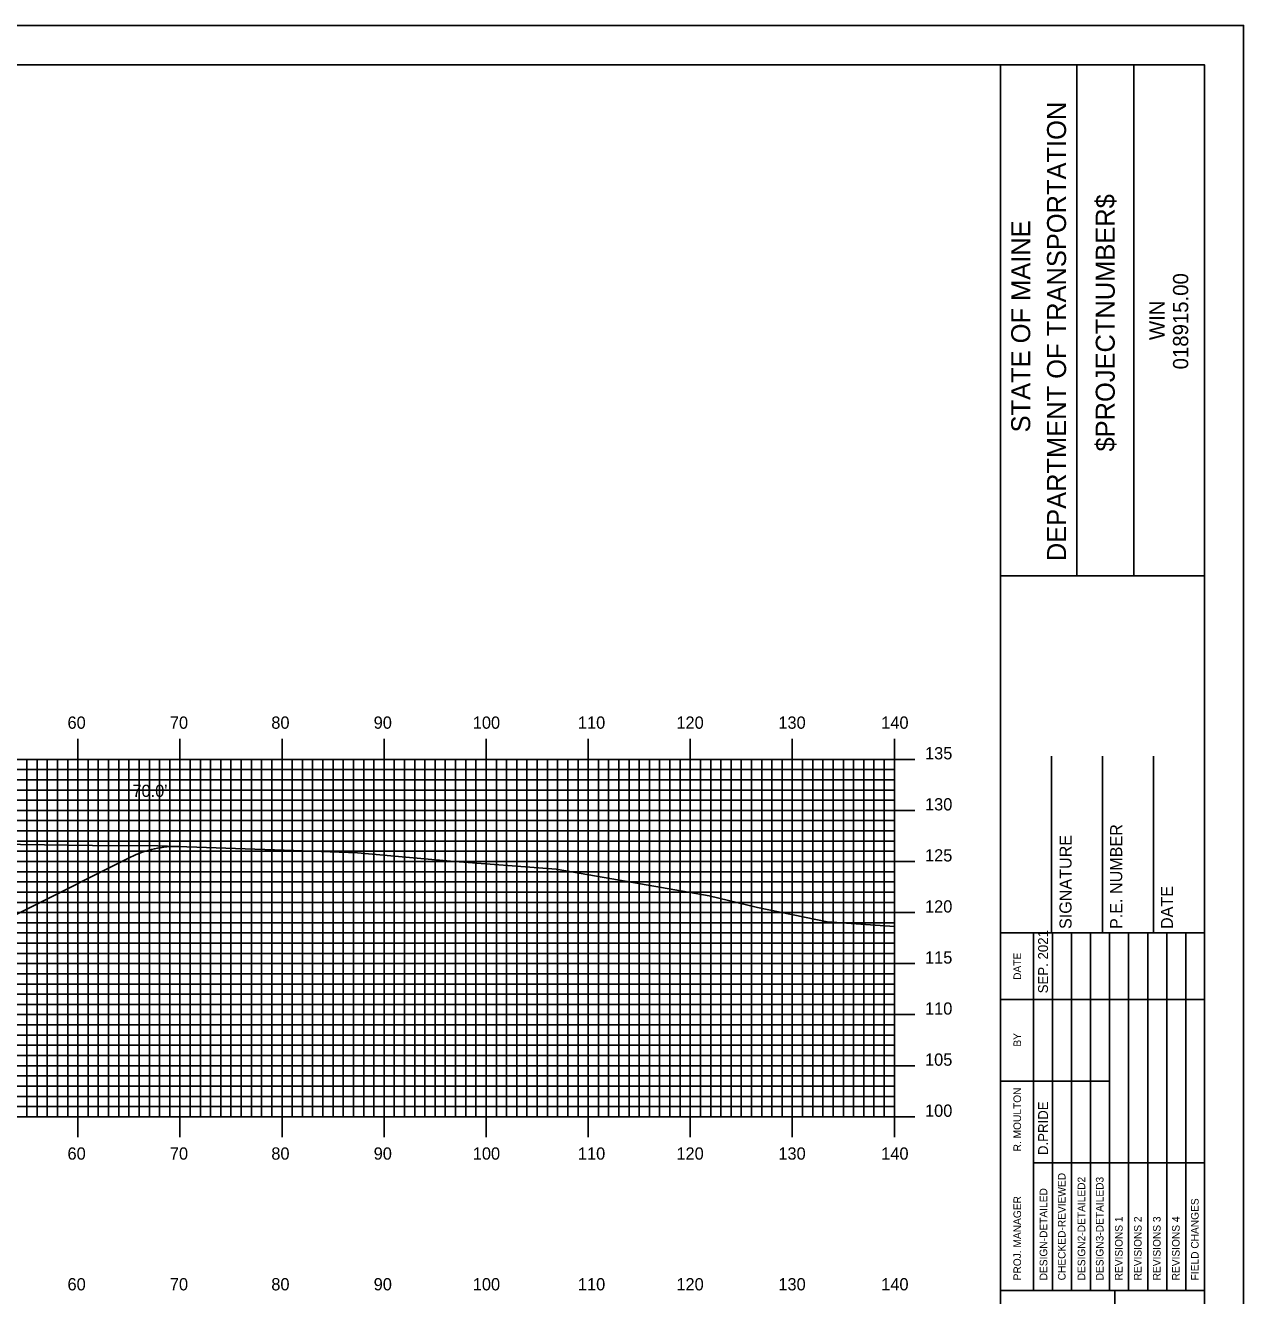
# Model space of a CAD drawing. Extents: x 1766907 to 1767250, y 442591 to 442811.
# Drawn here: x 1767127.3 to 1767246.6, y 442686.2 to 442810.5 of the extents above; entities that cross this region are included whole.
import ezdxf

# ---------------------------------------------------------------- set-up
doc = ezdxf.new("R2010")
doc.units = 0
for name, color, linetype in [('BORDER', 7, 'Continuous'), ('D_Roadway_Centerline', 7, 'Continuous'), ('D_Roadway_SlopeLines', 7, 'Continuous'), ('D_Text_Standard', 7, 'Continuous'), ('H_V ANNOTATION', 7, 'Continuous'), ('MAJOR', 7, 'Continuous'), ('MINOR', 7, 'Continuous'), ('PLOT BOUNDARY', 7, 'Continuous'), ('S_Roadway_Centerline', 7, 'Continuous')]:
    doc.layers.add(name, color=color, linetype=linetype)

msp = doc.modelspace()

# ---------------------------------------------------------------- linework, layer by layer
at = {"layer": 'BORDER'}
for p, q in [((1767222.82, 442596.67), (1767222.82, 442806.67)), ((1767230.28, 442756.66), (1767230.28, 442806.66)), ((1767235.87, 442756.66), (1767235.87, 442806.66)), ((1767222.83, 442756.65), (1767242.82, 442756.65)), ((1767227.82, 442721.67), (1767227.82, 442738.97)), ((1767232.82, 442721.67), (1767232.82, 442738.97)), ((1767237.82, 442721.67), (1767237.82, 442738.97)), ((1767222.82, 442721.67), (1767242.82, 442721.67)), ((1767222.82, 442686.67), (1767242.82, 442686.67)), ((1767234.01, 442616.67), (1767234.01, 442686.67))]:
    msp.add_line(p, q, dxfattribs=at)
msp.add_lwpolyline([(1766922.82, 442596.67), (1767242.82, 442596.67), (1767242.82, 442806.67), (1766922.82, 442806.67)], close=True, dxfattribs=at)
for points in [[(1767226.05, 442715.17), (1767226.05, 442721.67)], [(1767227.92, 442686.68), (1767227.92, 442721.67)], [(1767229.78, 442721.67), (1767229.78, 442686.68)], [(1767231.64, 442686.68), (1767231.64, 442721.67)], [(1767233.51, 442686.68), (1767233.51, 442721.67)], [(1767235.37, 442686.68), (1767235.37, 442721.67)], [(1767237.24, 442686.68), (1767237.24, 442721.67)], [(1767239.1, 442686.68), (1767239.1, 442721.67)], [(1767240.96, 442686.68), (1767240.96, 442721.67)], [(1767226.05, 442686.68), (1767226.05, 442720.26)], [(1767222.82, 442715.17), (1767242.82, 442715.17)], [(1767222.82, 442707.17), (1767226.05, 442707.17)], [(1767226.05, 442707.17), (1767233.51, 442707.17)], [(1767226.05, 442699.17), (1767242.82, 442699.17)]]:
    msp.add_lwpolyline(points, dxfattribs=at)
at = {"layer": 'D_Roadway_Centerline'}
msp.add_arc((1767142.05, 442720.14), 10, 88.0666, 116.5694, dxfattribs=at)
at = {"layer": 'D_Roadway_SlopeLines'}
msp.add_lwpolyline([(1767106.6, 442713.59), (1767137.58, 442729.09)], dxfattribs=at)
at = {"layer": 'MAJOR'}
for p, q in [((1767132.42, 442740.67), (1767132.42, 442738.67)), ((1767142.42, 442740.67), (1767142.42, 442738.67)), ((1767152.42, 442740.67), (1767152.42, 442738.67)), ((1767162.42, 442740.67), (1767162.42, 442738.67)), ((1767172.42, 442740.67), (1767172.42, 442738.67)), ((1767182.42, 442740.67), (1767182.42, 442738.67)), ((1767192.42, 442740.67), (1767192.42, 442738.67)), ((1767202.42, 442740.67), (1767202.42, 442738.67)), ((1767212.42, 442740.67), (1767212.42, 442738.67)), ((1766932.42, 442738.67), (1767212.42, 442738.67)), ((1766932.42, 442738.67), (1767212.42, 442738.67)), ((1767132.42, 442703.67), (1767132.42, 442738.67)), ((1767142.42, 442703.67), (1767142.42, 442738.67)), ((1767152.42, 442703.67), (1767152.42, 442738.67)), ((1767162.42, 442703.67), (1767162.42, 442738.67)), ((1767172.42, 442703.67), (1767172.42, 442738.67)), ((1767182.42, 442703.67), (1767182.42, 442738.67)), ((1767192.42, 442703.67), (1767192.42, 442738.67)), ((1767202.42, 442703.67), (1767202.42, 442738.67)), ((1767214.43, 442738.67), (1767210.42, 442738.67)), ((1767212.42, 442703.67), (1767212.42, 442738.67)), ((1767212.42, 442703.67), (1767212.42, 442738.67)), ((1766932.42, 442733.67), (1767212.42, 442733.67)), ((1767214.43, 442733.67), (1767210.42, 442733.67)), ((1766932.42, 442728.67), (1767212.42, 442728.67)), ((1767214.43, 442728.67), (1767210.42, 442728.67)), ((1766932.42, 442723.67), (1767212.42, 442723.67)), ((1767214.43, 442723.67), (1767210.42, 442723.67)), ((1766932.42, 442718.67), (1767212.42, 442718.67)), ((1767214.43, 442718.67), (1767210.42, 442718.67)), ((1766932.42, 442713.67), (1767212.42, 442713.67)), ((1767214.43, 442713.67), (1767210.42, 442713.67)), ((1766932.42, 442708.67), (1767212.42, 442708.67)), ((1767214.43, 442708.67), (1767210.42, 442708.67)), ((1766932.42, 442703.67), (1767212.42, 442703.67)), ((1766932.42, 442703.67), (1767212.42, 442703.67)), ((1767132.42, 442701.66), (1767132.42, 442703.67)), ((1767142.42, 442701.66), (1767142.42, 442703.67)), ((1767152.42, 442701.66), (1767152.42, 442703.67)), ((1767162.42, 442701.66), (1767162.42, 442703.67)), ((1767172.42, 442701.66), (1767172.42, 442703.67)), ((1767182.42, 442701.66), (1767182.42, 442703.67)), ((1767192.42, 442701.66), (1767192.42, 442703.67)), ((1767202.42, 442701.66), (1767202.42, 442703.67)), ((1767214.43, 442703.67), (1767210.42, 442703.67)), ((1767212.42, 442701.66), (1767212.42, 442703.67))]:
    msp.add_line(p, q, dxfattribs=at)
at = {"layer": 'MINOR'}
for p, q in [((1766932.42, 442737.67), (1767212.42, 442737.67)), ((1767127.42, 442703.67), (1767127.42, 442738.67)), ((1767128.42, 442703.67), (1767128.42, 442738.67)), ((1767129.42, 442703.67), (1767129.42, 442738.67)), ((1767130.42, 442703.67), (1767130.42, 442738.67)), ((1767131.42, 442703.67), (1767131.42, 442738.67)), ((1767133.42, 442703.67), (1767133.42, 442738.67)), ((1767134.42, 442703.67), (1767134.42, 442738.67)), ((1767135.42, 442703.67), (1767135.42, 442738.67)), ((1767136.42, 442703.67), (1767136.42, 442738.67)), ((1767137.42, 442703.67), (1767137.42, 442738.67)), ((1767138.42, 442703.67), (1767138.42, 442738.67)), ((1767139.42, 442703.67), (1767139.42, 442738.67)), ((1767140.42, 442703.67), (1767140.42, 442738.67)), ((1767141.42, 442703.67), (1767141.42, 442738.67)), ((1767143.42, 442703.67), (1767143.42, 442738.67)), ((1767144.42, 442703.67), (1767144.42, 442738.67)), ((1767145.42, 442703.67), (1767145.42, 442738.67)), ((1767146.42, 442703.67), (1767146.42, 442738.67)), ((1767147.42, 442703.67), (1767147.42, 442738.67)), ((1767148.42, 442703.67), (1767148.42, 442738.67)), ((1767149.42, 442703.67), (1767149.42, 442738.67)), ((1767150.42, 442703.67), (1767150.42, 442738.67)), ((1767151.42, 442703.67), (1767151.42, 442738.67)), ((1767153.42, 442703.67), (1767153.42, 442738.67)), ((1767154.42, 442703.67), (1767154.42, 442738.67)), ((1767155.42, 442703.67), (1767155.42, 442738.67)), ((1767156.42, 442703.67), (1767156.42, 442738.67)), ((1767157.42, 442703.67), (1767157.42, 442738.67)), ((1767158.42, 442703.67), (1767158.42, 442738.67)), ((1767159.42, 442703.67), (1767159.42, 442738.67)), ((1767160.42, 442703.67), (1767160.42, 442738.67)), ((1767161.42, 442703.67), (1767161.42, 442738.67)), ((1767163.42, 442703.67), (1767163.42, 442738.67)), ((1767164.42, 442703.67), (1767164.42, 442738.67)), ((1767165.42, 442703.67), (1767165.42, 442738.67)), ((1767166.42, 442703.67), (1767166.42, 442738.67)), ((1767167.42, 442703.67), (1767167.42, 442738.67)), ((1767168.42, 442703.67), (1767168.42, 442738.67)), ((1767169.42, 442703.67), (1767169.42, 442738.67)), ((1767170.42, 442703.67), (1767170.42, 442738.67)), ((1767171.42, 442703.67), (1767171.42, 442738.67)), ((1767173.42, 442703.67), (1767173.42, 442738.67)), ((1767174.42, 442703.67), (1767174.42, 442738.67)), ((1767175.42, 442703.67), (1767175.42, 442738.67)), ((1767176.42, 442703.67), (1767176.42, 442738.67)), ((1767177.42, 442703.67), (1767177.42, 442738.67)), ((1767178.42, 442703.67), (1767178.42, 442738.67)), ((1767179.42, 442703.67), (1767179.42, 442738.67)), ((1767180.42, 442703.67), (1767180.42, 442738.67)), ((1767181.42, 442703.67), (1767181.42, 442738.67)), ((1767183.42, 442703.67), (1767183.42, 442738.67)), ((1767184.42, 442703.67), (1767184.42, 442738.67)), ((1767185.42, 442703.67), (1767185.42, 442738.67)), ((1767186.42, 442703.67), (1767186.42, 442738.67)), ((1767187.42, 442703.67), (1767187.42, 442738.67)), ((1767188.42, 442703.67), (1767188.42, 442738.67)), ((1767189.42, 442703.67), (1767189.42, 442738.67)), ((1767190.42, 442703.67), (1767190.42, 442738.67)), ((1767191.42, 442703.67), (1767191.42, 442738.67)), ((1767193.42, 442703.67), (1767193.42, 442738.67)), ((1767194.42, 442703.67), (1767194.42, 442738.67)), ((1767195.42, 442703.67), (1767195.42, 442738.67)), ((1767196.42, 442703.67), (1767196.42, 442738.67)), ((1767197.42, 442703.67), (1767197.42, 442738.67)), ((1767198.42, 442703.67), (1767198.42, 442738.67)), ((1767199.42, 442703.67), (1767199.42, 442738.67)), ((1767200.42, 442703.67), (1767200.42, 442738.67)), ((1767201.42, 442703.67), (1767201.42, 442738.67)), ((1767203.42, 442703.67), (1767203.42, 442738.67)), ((1767204.42, 442703.67), (1767204.42, 442738.67)), ((1767205.42, 442703.67), (1767205.42, 442738.67)), ((1767206.42, 442703.67), (1767206.42, 442738.67)), ((1767207.42, 442703.67), (1767207.42, 442738.67)), ((1767208.42, 442703.67), (1767208.42, 442738.67)), ((1767209.42, 442703.67), (1767209.42, 442738.67)), ((1767210.42, 442703.67), (1767210.42, 442738.67)), ((1767212.42, 442737.67), (1767210.42, 442737.67)), ((1767211.42, 442703.67), (1767211.42, 442738.67)), ((1766932.42, 442736.67), (1767212.42, 442736.67)), ((1767212.42, 442736.67), (1767210.42, 442736.67)), ((1766932.42, 442735.67), (1767212.42, 442735.67)), ((1767212.42, 442735.67), (1767210.42, 442735.67)), ((1766932.42, 442734.67), (1767212.42, 442734.67)), ((1767212.42, 442734.67), (1767210.42, 442734.67)), ((1766932.42, 442732.67), (1767212.42, 442732.67)), ((1767212.42, 442732.67), (1767210.42, 442732.67)), ((1766932.42, 442731.67), (1767212.42, 442731.67)), ((1767212.42, 442731.67), (1767210.42, 442731.67)), ((1766932.42, 442730.67), (1767212.42, 442730.67)), ((1767212.42, 442730.67), (1767210.42, 442730.67)), ((1766932.42, 442729.67), (1767212.42, 442729.67)), ((1767212.42, 442729.67), (1767210.42, 442729.67)), ((1766932.42, 442727.67), (1767212.42, 442727.67)), ((1767212.42, 442727.67), (1767210.42, 442727.67)), ((1766932.42, 442726.67), (1767212.42, 442726.67)), ((1767212.42, 442726.67), (1767210.42, 442726.67)), ((1766932.42, 442725.67), (1767212.42, 442725.67)), ((1767212.42, 442725.67), (1767210.42, 442725.67)), ((1766932.42, 442724.67), (1767212.42, 442724.67)), ((1767212.42, 442724.67), (1767210.42, 442724.67)), ((1766932.42, 442722.67), (1767212.42, 442722.67)), ((1767212.42, 442722.67), (1767210.42, 442722.67)), ((1766932.42, 442721.67), (1767212.42, 442721.67)), ((1767212.42, 442721.67), (1767210.42, 442721.67)), ((1766932.42, 442720.67), (1767212.42, 442720.67)), ((1767212.42, 442720.67), (1767210.42, 442720.67)), ((1766932.42, 442719.67), (1767212.42, 442719.67)), ((1767212.42, 442719.67), (1767210.42, 442719.67)), ((1766932.42, 442717.67), (1767212.42, 442717.67)), ((1767212.42, 442717.67), (1767210.42, 442717.67)), ((1766932.42, 442716.67), (1767212.42, 442716.67)), ((1767212.42, 442716.67), (1767210.42, 442716.67)), ((1766932.42, 442715.67), (1767212.42, 442715.67)), ((1767212.42, 442715.67), (1767210.42, 442715.67)), ((1766932.42, 442714.67), (1767212.42, 442714.67)), ((1767212.42, 442714.67), (1767210.42, 442714.67)), ((1766932.42, 442712.67), (1767212.42, 442712.67)), ((1767212.42, 442712.67), (1767210.42, 442712.67)), ((1766932.42, 442711.67), (1767212.42, 442711.67)), ((1767212.42, 442711.67), (1767210.42, 442711.67)), ((1766932.42, 442710.67), (1767212.42, 442710.67)), ((1767212.42, 442710.67), (1767210.42, 442710.67)), ((1766932.42, 442709.67), (1767212.42, 442709.67)), ((1767212.42, 442709.67), (1767210.42, 442709.67)), ((1766932.42, 442707.67), (1767212.42, 442707.67)), ((1766932.42, 442706.67), (1767212.42, 442706.67)), ((1767212.42, 442707.67), (1767210.42, 442707.67)), ((1767212.42, 442706.67), (1767210.42, 442706.67)), ((1766932.42, 442705.67), (1767212.42, 442705.67)), ((1767212.42, 442705.67), (1767210.42, 442705.67)), ((1766932.42, 442704.67), (1767212.42, 442704.67)), ((1767212.42, 442704.67), (1767210.42, 442704.67))]:
    msp.add_line(p, q, dxfattribs=at)
at = {"layer": 'PLOT BOUNDARY'}
msp.add_lwpolyline([(1766906.64, 442590.55), (1767246.64, 442590.55), (1767246.64, 442810.55), (1766906.64, 442810.55)], close=True, dxfattribs=at)
at = {"layer": 'S_Roadway_Centerline'}
msp.add_lwpolyline([(1767122.07, 442730.41), (1767133.86, 442730.25), (1767140.26, 442730.21), (1767153.58, 442729.76), (1767159.8, 442729.53), (1767168.93, 442728.71), (1767179.28, 442727.91), (1767186.25, 442726.72), (1767194.26, 442725.32), (1767199.02, 442724.17), (1767205.84, 442722.77), (1767212.42, 442722.3)], dxfattribs=at)

# ---------------------------------------------------------------- texts
at = {"layer": 'BORDER'}
for s, height, p in [('DEPARTMENT OF TRANSPORTATION', 1.8635, (1767229.24, 442758.08)), ('$PROJECTNUMBER$', 1.8635, (1767234.01, 442768.82)), ('STATE OF MAINE', 1.8635, (1767225.73, 442770.69)), ('018915.00', 1.491, (1767241.21, 442776.86)), ('WIN', 1.491, (1767238.9, 442779.73)), ('P.E. NUMBER', 1.1811, (1767234.74, 442722.06)), ('SIGNATURE', 1.181, (1767229.78, 442722.06)), ('DATE', 1.181, (1767239.71, 442722.06)), ('SEP. 2021', 0.969, (1767227.47, 442715.76)), ('DATE', 0.743, (1767224.83, 442717.08)), ('BY', 0.743, (1767224.83, 442710.54)), ('R. MOULTON', 0.745, (1767224.83, 442700.28)), ('D.PRIDE', 0.969, (1767227.47, 442699.92)), ('CHECKED-REVIEWED', 0.7455, (1767229.19, 442687.65)), ('DESIGN2-DETAILED2', 0.7455, (1767231.12, 442687.65)), ('DESIGN3-DETAILED3', 0.7455, (1767232.91, 442687.65)), ('DESIGN-DETAILED', 0.7455, (1767227.4, 442687.65)), ('PROJ. MANAGER', 0.7455, (1767224.83, 442687.65)), ('FIELD CHANGES', 0.7455, (1767242.23, 442687.65)), ('REVISIONS 1', 0.7455, (1767234.78, 442687.65)), ('REVISIONS 2', 0.7455, (1767236.64, 442687.65)), ('REVISIONS 3', 0.7455, (1767238.5, 442687.65)), ('REVISIONS 4', 0.7455, (1767240.37, 442687.65))]:
    msp.add_text(s, height=height, rotation=90, dxfattribs=at).set_placement(p)
at = {"layer": 'D_Text_Standard'}
msp.add_text("70.0'", height=1.2, dxfattribs=at).set_placement((1767137.76, 442734.99))
at = {"layer": 'H_V ANNOTATION'}
for s, p in [('60', (1767131.4, 442741.67)), ('70', (1767141.43, 442741.67)), ('80', (1767151.37, 442741.67)), ('90', (1767161.4, 442741.67)), ('100', (1767171.11, 442741.67)), ('110', (1767181.41, 442741.67)), ('120', (1767191.06, 442741.67)), ('130', (1767201.05, 442741.67)), ('140', (1767211.13, 442741.67)), ('135', (1767215.42, 442738.67)), ('130', (1767215.42, 442733.67)), ('125', (1767215.42, 442728.67)), ('120', (1767215.42, 442723.67)), ('115', (1767215.42, 442718.67)), ('110', (1767215.42, 442713.67)), ('105', (1767215.42, 442708.67)), ('100', (1767215.42, 442703.67)), ('60', (1767131.4, 442699.47)), ('70', (1767141.43, 442699.47)), ('80', (1767151.37, 442699.47)), ('90', (1767161.4, 442699.47)), ('100', (1767171.11, 442699.47)), ('110', (1767181.41, 442699.47)), ('120', (1767191.06, 442699.47)), ('130', (1767201.05, 442699.47)), ('140', (1767211.13, 442699.47)), ('60', (1767131.4, 442686.67)), ('70', (1767141.43, 442686.67)), ('80', (1767151.37, 442686.67)), ('90', (1767161.4, 442686.67)), ('100', (1767171.11, 442686.67)), ('110', (1767181.41, 442686.67)), ('120', (1767191.06, 442686.67)), ('130', (1767201.05, 442686.67)), ('140', (1767211.13, 442686.67))]:
    msp.add_text(s, height=1.2, dxfattribs=at).set_placement(p)

doc.saveas('drawing.dxf')
